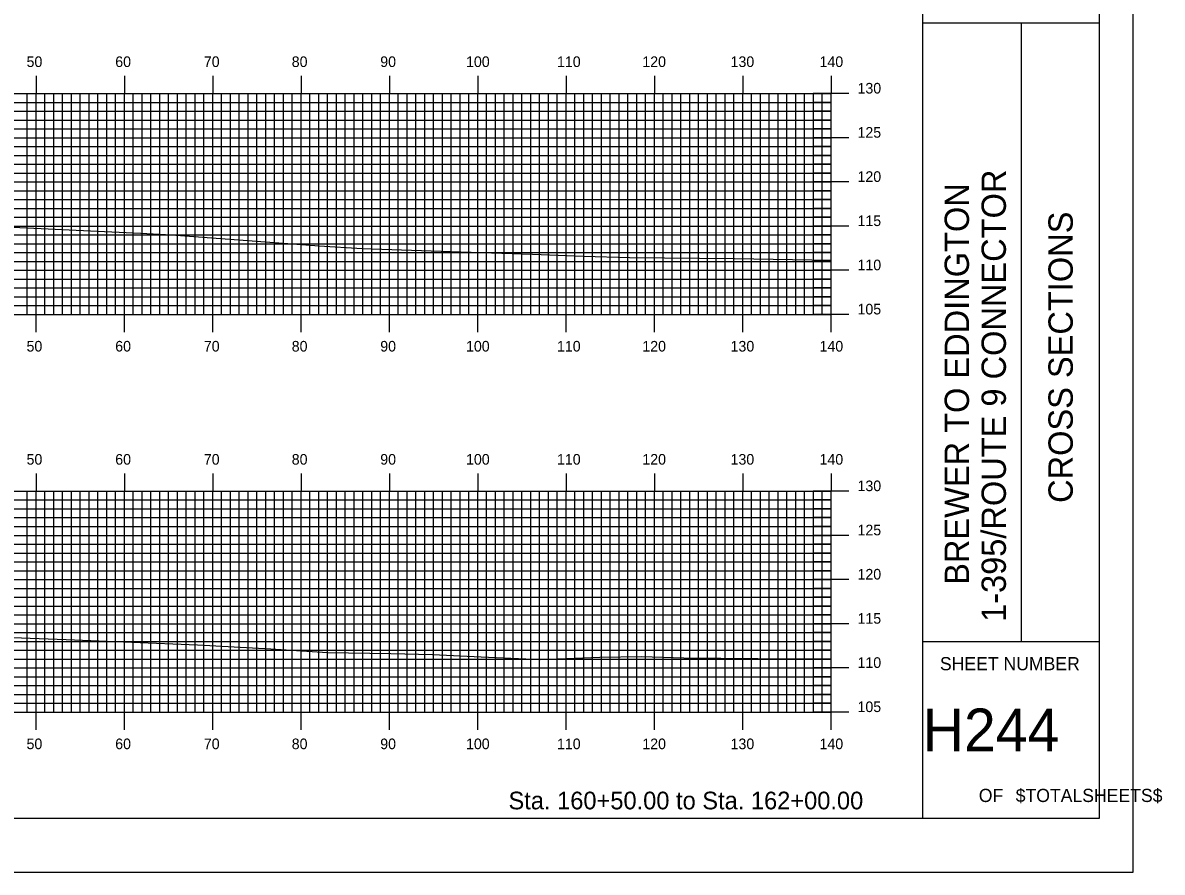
# Model space of a CAD drawing. Extents: x 1780286 to 1780629, y 442591 to 442811.
# Drawn here: x 1780500.4 to 1780629.4, y 442590.5 to 442686.7 of the extents above; entities that cross this region are included whole.
import ezdxf

# ---------------------------------------------------------------- set-up
doc = ezdxf.new("R2010")
doc.units = 0
for name, color, linetype in [('BORDER', 7, 'Continuous'), ('H_V ANNOTATION', 7, 'Continuous'), ('MAJOR', 7, 'Continuous'), ('MINOR', 7, 'Continuous'), ('PLOT BOUNDARY', 7, 'Continuous'), ('S_Roadway_Centerline', 7, 'Continuous')]:
    doc.layers.add(name, color=color, linetype=linetype)

msp = doc.modelspace()

# ---------------------------------------------------------------- linework, layer by layer
at = {"layer": 'BORDER'}
for p, q in [((1780602.27, 442596.67), (1780602.27, 442806.67)), ((1780602.27, 442686.67), (1780622.27, 442686.67)), ((1780613.45, 442616.67), (1780613.45, 442686.67)), ((1780602.27, 442616.67), (1780622.27, 442616.67))]:
    msp.add_line(p, q, dxfattribs=at)
msp.add_lwpolyline([(1780302.27, 442596.67), (1780622.27, 442596.67), (1780622.27, 442806.67), (1780302.27, 442806.67)], close=True, dxfattribs=at)
at = {"layer": 'MAJOR'}
for p, q in [((1780501.87, 442680.67), (1780501.87, 442678.67)), ((1780511.87, 442680.67), (1780511.87, 442678.67)), ((1780521.87, 442680.67), (1780521.87, 442678.67)), ((1780531.87, 442680.67), (1780531.87, 442678.67)), ((1780541.87, 442680.67), (1780541.87, 442678.67)), ((1780551.87, 442680.67), (1780551.87, 442678.67)), ((1780561.87, 442680.67), (1780561.87, 442678.67)), ((1780571.87, 442680.67), (1780571.87, 442678.67)), ((1780581.87, 442680.67), (1780581.87, 442678.67)), ((1780591.87, 442680.67), (1780591.87, 442678.67)), ((1780311.87, 442678.67), (1780591.87, 442678.67)), ((1780311.87, 442678.67), (1780591.87, 442678.67)), ((1780501.87, 442653.67), (1780501.87, 442678.67)), ((1780511.87, 442653.67), (1780511.87, 442678.67)), ((1780521.87, 442653.67), (1780521.87, 442678.67)), ((1780531.87, 442653.67), (1780531.87, 442678.67)), ((1780541.87, 442653.67), (1780541.87, 442678.67)), ((1780551.87, 442653.67), (1780551.87, 442678.67)), ((1780561.87, 442653.67), (1780561.87, 442678.67)), ((1780571.87, 442653.67), (1780571.87, 442678.67)), ((1780581.87, 442653.67), (1780581.87, 442678.67)), ((1780593.87, 442678.67), (1780589.86, 442678.67)), ((1780591.87, 442653.67), (1780591.87, 442678.67)), ((1780591.87, 442653.67), (1780591.87, 442678.67)), ((1780311.87, 442673.67), (1780591.87, 442673.67)), ((1780593.87, 442673.67), (1780589.86, 442673.67)), ((1780311.87, 442668.67), (1780591.87, 442668.67)), ((1780593.87, 442668.67), (1780589.86, 442668.67)), ((1780311.87, 442663.67), (1780591.87, 442663.67)), ((1780593.87, 442663.67), (1780589.86, 442663.67)), ((1780311.87, 442658.67), (1780591.87, 442658.67)), ((1780593.87, 442658.67), (1780589.86, 442658.67)), ((1780311.87, 442653.67), (1780591.87, 442653.67)), ((1780311.87, 442653.67), (1780591.87, 442653.67)), ((1780501.87, 442651.66), (1780501.87, 442653.67)), ((1780511.87, 442651.66), (1780511.87, 442653.67)), ((1780521.87, 442651.66), (1780521.87, 442653.67)), ((1780531.87, 442651.66), (1780531.87, 442653.67)), ((1780541.87, 442651.66), (1780541.87, 442653.67)), ((1780551.87, 442651.66), (1780551.87, 442653.67)), ((1780561.87, 442651.66), (1780561.87, 442653.67)), ((1780571.87, 442651.66), (1780571.87, 442653.67)), ((1780581.87, 442651.66), (1780581.87, 442653.67)), ((1780593.87, 442653.67), (1780589.86, 442653.67)), ((1780591.87, 442651.66), (1780591.87, 442653.67)), ((1780501.87, 442635.67), (1780501.87, 442633.67)), ((1780511.87, 442635.67), (1780511.87, 442633.67)), ((1780521.87, 442635.67), (1780521.87, 442633.67)), ((1780531.87, 442635.67), (1780531.87, 442633.67)), ((1780541.87, 442635.67), (1780541.87, 442633.67)), ((1780551.87, 442635.67), (1780551.87, 442633.67)), ((1780561.87, 442635.67), (1780561.87, 442633.67)), ((1780571.87, 442635.67), (1780571.87, 442633.67)), ((1780581.87, 442635.67), (1780581.87, 442633.67)), ((1780591.87, 442635.67), (1780591.87, 442633.67)), ((1780311.87, 442633.67), (1780591.87, 442633.67)), ((1780311.87, 442633.67), (1780591.87, 442633.67)), ((1780501.87, 442608.67), (1780501.87, 442633.67)), ((1780511.87, 442608.67), (1780511.87, 442633.67)), ((1780521.87, 442608.67), (1780521.87, 442633.67)), ((1780531.87, 442608.67), (1780531.87, 442633.67)), ((1780541.87, 442608.67), (1780541.87, 442633.67)), ((1780551.87, 442608.67), (1780551.87, 442633.67)), ((1780561.87, 442608.67), (1780561.87, 442633.67)), ((1780571.87, 442608.67), (1780571.87, 442633.67)), ((1780581.87, 442608.67), (1780581.87, 442633.67)), ((1780593.87, 442633.67), (1780589.86, 442633.67)), ((1780591.87, 442608.67), (1780591.87, 442633.67)), ((1780591.87, 442608.67), (1780591.87, 442633.67)), ((1780311.87, 442628.67), (1780591.87, 442628.67)), ((1780593.87, 442628.67), (1780589.86, 442628.67)), ((1780311.87, 442623.67), (1780591.87, 442623.67)), ((1780593.87, 442623.67), (1780589.86, 442623.67)), ((1780311.87, 442618.67), (1780591.87, 442618.67)), ((1780593.87, 442618.67), (1780589.86, 442618.67)), ((1780311.87, 442613.67), (1780591.87, 442613.67)), ((1780593.87, 442613.67), (1780589.86, 442613.67)), ((1780311.87, 442608.67), (1780591.87, 442608.67)), ((1780311.87, 442608.67), (1780591.87, 442608.67)), ((1780501.87, 442606.66), (1780501.87, 442608.67)), ((1780511.87, 442606.66), (1780511.87, 442608.67)), ((1780521.87, 442606.66), (1780521.87, 442608.67)), ((1780531.87, 442606.66), (1780531.87, 442608.67)), ((1780541.87, 442606.66), (1780541.87, 442608.67)), ((1780551.87, 442606.66), (1780551.87, 442608.67)), ((1780561.87, 442606.66), (1780561.87, 442608.67)), ((1780571.87, 442606.66), (1780571.87, 442608.67)), ((1780581.87, 442606.66), (1780581.87, 442608.67)), ((1780593.87, 442608.67), (1780589.86, 442608.67)), ((1780591.87, 442606.66), (1780591.87, 442608.67))]:
    msp.add_line(p, q, dxfattribs=at)
at = {"layer": 'MINOR'}
for p, q in [((1780500.87, 442653.67), (1780500.87, 442678.67)), ((1780502.87, 442653.67), (1780502.87, 442678.67)), ((1780503.87, 442653.67), (1780503.87, 442678.67)), ((1780504.87, 442653.67), (1780504.87, 442678.67)), ((1780505.87, 442653.67), (1780505.87, 442678.67)), ((1780506.87, 442653.67), (1780506.87, 442678.67)), ((1780507.87, 442653.67), (1780507.87, 442678.67)), ((1780508.87, 442653.67), (1780508.87, 442678.67)), ((1780509.87, 442653.67), (1780509.87, 442678.67)), ((1780510.87, 442653.67), (1780510.87, 442678.67)), ((1780512.87, 442653.67), (1780512.87, 442678.67)), ((1780513.87, 442653.67), (1780513.87, 442678.67)), ((1780514.87, 442653.67), (1780514.87, 442678.67)), ((1780515.87, 442653.67), (1780515.87, 442678.67)), ((1780516.87, 442653.67), (1780516.87, 442678.67)), ((1780517.87, 442653.67), (1780517.87, 442678.67)), ((1780518.87, 442653.67), (1780518.87, 442678.67)), ((1780519.87, 442653.67), (1780519.87, 442678.67)), ((1780520.87, 442653.67), (1780520.87, 442678.67)), ((1780522.87, 442653.67), (1780522.87, 442678.67)), ((1780523.87, 442653.67), (1780523.87, 442678.67)), ((1780524.87, 442653.67), (1780524.87, 442678.67)), ((1780525.87, 442653.67), (1780525.87, 442678.67)), ((1780526.87, 442653.67), (1780526.87, 442678.67)), ((1780527.87, 442653.67), (1780527.87, 442678.67)), ((1780528.87, 442653.67), (1780528.87, 442678.67)), ((1780529.87, 442653.67), (1780529.87, 442678.67)), ((1780530.87, 442653.67), (1780530.87, 442678.67)), ((1780532.87, 442653.67), (1780532.87, 442678.67)), ((1780533.87, 442653.67), (1780533.87, 442678.67)), ((1780534.87, 442653.67), (1780534.87, 442678.67)), ((1780535.87, 442653.67), (1780535.87, 442678.67)), ((1780536.87, 442653.67), (1780536.87, 442678.67)), ((1780537.87, 442653.67), (1780537.87, 442678.67)), ((1780538.87, 442653.67), (1780538.87, 442678.67)), ((1780539.87, 442653.67), (1780539.87, 442678.67)), ((1780540.87, 442653.67), (1780540.87, 442678.67)), ((1780542.87, 442653.67), (1780542.87, 442678.67)), ((1780543.87, 442653.67), (1780543.87, 442678.67)), ((1780544.87, 442653.67), (1780544.87, 442678.67)), ((1780545.87, 442653.67), (1780545.87, 442678.67)), ((1780546.87, 442653.67), (1780546.87, 442678.67)), ((1780547.87, 442653.67), (1780547.87, 442678.67)), ((1780548.87, 442653.67), (1780548.87, 442678.67)), ((1780549.87, 442653.67), (1780549.87, 442678.67)), ((1780550.87, 442653.67), (1780550.87, 442678.67)), ((1780552.87, 442653.67), (1780552.87, 442678.67)), ((1780553.87, 442653.67), (1780553.87, 442678.67)), ((1780554.87, 442653.67), (1780554.87, 442678.67)), ((1780555.87, 442653.67), (1780555.87, 442678.67)), ((1780556.87, 442653.67), (1780556.87, 442678.67)), ((1780557.87, 442653.67), (1780557.87, 442678.67)), ((1780558.87, 442653.67), (1780558.87, 442678.67)), ((1780559.87, 442653.67), (1780559.87, 442678.67)), ((1780560.87, 442653.67), (1780560.87, 442678.67)), ((1780562.87, 442653.67), (1780562.87, 442678.67)), ((1780563.87, 442653.67), (1780563.87, 442678.67)), ((1780564.87, 442653.67), (1780564.87, 442678.67)), ((1780565.87, 442653.67), (1780565.87, 442678.67)), ((1780566.87, 442653.67), (1780566.87, 442678.67)), ((1780567.87, 442653.67), (1780567.87, 442678.67)), ((1780568.87, 442653.67), (1780568.87, 442678.67)), ((1780569.87, 442653.67), (1780569.87, 442678.67)), ((1780570.87, 442653.67), (1780570.87, 442678.67)), ((1780572.87, 442653.67), (1780572.87, 442678.67)), ((1780573.87, 442653.67), (1780573.87, 442678.67)), ((1780574.87, 442653.67), (1780574.87, 442678.67)), ((1780575.87, 442653.67), (1780575.87, 442678.67)), ((1780576.87, 442653.67), (1780576.87, 442678.67)), ((1780577.87, 442653.67), (1780577.87, 442678.67)), ((1780578.87, 442653.67), (1780578.87, 442678.67)), ((1780579.87, 442653.67), (1780579.87, 442678.67)), ((1780580.87, 442653.67), (1780580.87, 442678.67)), ((1780582.87, 442653.67), (1780582.87, 442678.67)), ((1780583.87, 442653.67), (1780583.87, 442678.67)), ((1780584.87, 442653.67), (1780584.87, 442678.67)), ((1780585.87, 442653.67), (1780585.87, 442678.67)), ((1780586.87, 442653.67), (1780586.87, 442678.67)), ((1780587.87, 442653.67), (1780587.87, 442678.67)), ((1780588.87, 442653.67), (1780588.87, 442678.67)), ((1780589.87, 442653.67), (1780589.87, 442678.67)), ((1780590.87, 442653.67), (1780590.87, 442678.67)), ((1780311.87, 442677.67), (1780591.87, 442677.67)), ((1780591.87, 442677.67), (1780589.86, 442677.67)), ((1780311.87, 442676.67), (1780591.87, 442676.67)), ((1780591.87, 442676.67), (1780589.86, 442676.67)), ((1780311.87, 442675.67), (1780591.87, 442675.67)), ((1780311.87, 442674.67), (1780591.87, 442674.67)), ((1780591.87, 442675.67), (1780589.86, 442675.67)), ((1780591.87, 442674.67), (1780589.86, 442674.67)), ((1780311.87, 442672.67), (1780591.87, 442672.67)), ((1780591.87, 442672.67), (1780589.86, 442672.67)), ((1780311.87, 442671.67), (1780591.87, 442671.67)), ((1780311.87, 442670.67), (1780591.87, 442670.67)), ((1780591.87, 442671.67), (1780589.86, 442671.67)), ((1780591.87, 442670.67), (1780589.86, 442670.67)), ((1780311.87, 442669.67), (1780591.87, 442669.67)), ((1780591.87, 442669.67), (1780589.86, 442669.67)), ((1780311.87, 442667.67), (1780591.87, 442667.67)), ((1780591.87, 442667.67), (1780589.86, 442667.67)), ((1780311.87, 442666.67), (1780591.87, 442666.67)), ((1780311.87, 442665.67), (1780591.87, 442665.67)), ((1780591.87, 442666.67), (1780589.86, 442666.67)), ((1780591.87, 442665.67), (1780589.86, 442665.67)), ((1780311.87, 442664.67), (1780591.87, 442664.67)), ((1780591.87, 442664.67), (1780589.86, 442664.67)), ((1780311.87, 442662.67), (1780591.87, 442662.67)), ((1780311.87, 442661.67), (1780591.87, 442661.67)), ((1780591.87, 442662.67), (1780589.86, 442662.67)), ((1780591.87, 442661.67), (1780589.86, 442661.67)), ((1780311.87, 442660.67), (1780591.87, 442660.67)), ((1780591.87, 442660.67), (1780589.86, 442660.67)), ((1780311.87, 442659.67), (1780591.87, 442659.67)), ((1780591.87, 442659.67), (1780589.86, 442659.67)), ((1780311.87, 442657.67), (1780591.87, 442657.67)), ((1780311.87, 442656.67), (1780591.87, 442656.67)), ((1780591.87, 442657.67), (1780589.86, 442657.67)), ((1780591.87, 442656.67), (1780589.86, 442656.67)), ((1780311.87, 442655.67), (1780591.87, 442655.67)), ((1780591.87, 442655.67), (1780589.86, 442655.67)), ((1780311.87, 442654.67), (1780591.87, 442654.67)), ((1780591.87, 442654.67), (1780589.86, 442654.67)), ((1780500.87, 442608.67), (1780500.87, 442633.67)), ((1780502.87, 442608.67), (1780502.87, 442633.67)), ((1780503.87, 442608.67), (1780503.87, 442633.67)), ((1780504.87, 442608.67), (1780504.87, 442633.67)), ((1780505.87, 442608.67), (1780505.87, 442633.67)), ((1780506.87, 442608.67), (1780506.87, 442633.67)), ((1780507.87, 442608.67), (1780507.87, 442633.67)), ((1780508.87, 442608.67), (1780508.87, 442633.67)), ((1780509.87, 442608.67), (1780509.87, 442633.67)), ((1780510.87, 442608.67), (1780510.87, 442633.67)), ((1780512.87, 442608.67), (1780512.87, 442633.67)), ((1780513.87, 442608.67), (1780513.87, 442633.67)), ((1780514.87, 442608.67), (1780514.87, 442633.67)), ((1780515.87, 442608.67), (1780515.87, 442633.67)), ((1780516.87, 442608.67), (1780516.87, 442633.67)), ((1780517.87, 442608.67), (1780517.87, 442633.67)), ((1780518.87, 442608.67), (1780518.87, 442633.67)), ((1780519.87, 442608.67), (1780519.87, 442633.67)), ((1780520.87, 442608.67), (1780520.87, 442633.67)), ((1780522.87, 442608.67), (1780522.87, 442633.67)), ((1780523.87, 442608.67), (1780523.87, 442633.67)), ((1780524.87, 442608.67), (1780524.87, 442633.67)), ((1780525.87, 442608.67), (1780525.87, 442633.67)), ((1780526.87, 442608.67), (1780526.87, 442633.67)), ((1780527.87, 442608.67), (1780527.87, 442633.67)), ((1780528.87, 442608.67), (1780528.87, 442633.67)), ((1780529.87, 442608.67), (1780529.87, 442633.67)), ((1780530.87, 442608.67), (1780530.87, 442633.67)), ((1780532.87, 442608.67), (1780532.87, 442633.67)), ((1780533.87, 442608.67), (1780533.87, 442633.67)), ((1780534.87, 442608.67), (1780534.87, 442633.67)), ((1780535.87, 442608.67), (1780535.87, 442633.67)), ((1780536.87, 442608.67), (1780536.87, 442633.67)), ((1780537.87, 442608.67), (1780537.87, 442633.67)), ((1780538.87, 442608.67), (1780538.87, 442633.67)), ((1780539.87, 442608.67), (1780539.87, 442633.67)), ((1780540.87, 442608.67), (1780540.87, 442633.67)), ((1780542.87, 442608.67), (1780542.87, 442633.67)), ((1780543.87, 442608.67), (1780543.87, 442633.67)), ((1780544.87, 442608.67), (1780544.87, 442633.67)), ((1780545.87, 442608.67), (1780545.87, 442633.67)), ((1780546.87, 442608.67), (1780546.87, 442633.67)), ((1780547.87, 442608.67), (1780547.87, 442633.67)), ((1780548.87, 442608.67), (1780548.87, 442633.67)), ((1780549.87, 442608.67), (1780549.87, 442633.67)), ((1780550.87, 442608.67), (1780550.87, 442633.67)), ((1780552.87, 442608.67), (1780552.87, 442633.67)), ((1780553.87, 442608.67), (1780553.87, 442633.67)), ((1780554.87, 442608.67), (1780554.87, 442633.67)), ((1780555.87, 442608.67), (1780555.87, 442633.67)), ((1780556.87, 442608.67), (1780556.87, 442633.67)), ((1780557.87, 442608.67), (1780557.87, 442633.67)), ((1780558.87, 442608.67), (1780558.87, 442633.67)), ((1780559.87, 442608.67), (1780559.87, 442633.67)), ((1780560.87, 442608.67), (1780560.87, 442633.67)), ((1780562.87, 442608.67), (1780562.87, 442633.67)), ((1780563.87, 442608.67), (1780563.87, 442633.67)), ((1780564.87, 442608.67), (1780564.87, 442633.67)), ((1780565.87, 442608.67), (1780565.87, 442633.67)), ((1780566.87, 442608.67), (1780566.87, 442633.67)), ((1780567.87, 442608.67), (1780567.87, 442633.67)), ((1780568.87, 442608.67), (1780568.87, 442633.67)), ((1780569.87, 442608.67), (1780569.87, 442633.67)), ((1780570.87, 442608.67), (1780570.87, 442633.67)), ((1780572.87, 442608.67), (1780572.87, 442633.67)), ((1780573.87, 442608.67), (1780573.87, 442633.67)), ((1780574.87, 442608.67), (1780574.87, 442633.67)), ((1780575.87, 442608.67), (1780575.87, 442633.67)), ((1780576.87, 442608.67), (1780576.87, 442633.67)), ((1780577.87, 442608.67), (1780577.87, 442633.67)), ((1780578.87, 442608.67), (1780578.87, 442633.67)), ((1780579.87, 442608.67), (1780579.87, 442633.67)), ((1780580.87, 442608.67), (1780580.87, 442633.67)), ((1780582.87, 442608.67), (1780582.87, 442633.67)), ((1780583.87, 442608.67), (1780583.87, 442633.67)), ((1780584.87, 442608.67), (1780584.87, 442633.67)), ((1780585.87, 442608.67), (1780585.87, 442633.67)), ((1780586.87, 442608.67), (1780586.87, 442633.67)), ((1780587.87, 442608.67), (1780587.87, 442633.67)), ((1780588.87, 442608.67), (1780588.87, 442633.67)), ((1780589.87, 442608.67), (1780589.87, 442633.67)), ((1780590.87, 442608.67), (1780590.87, 442633.67)), ((1780311.87, 442632.67), (1780591.87, 442632.67)), ((1780591.87, 442632.67), (1780589.86, 442632.67)), ((1780311.87, 442631.67), (1780591.87, 442631.67)), ((1780311.87, 442630.67), (1780591.87, 442630.67)), ((1780591.87, 442631.67), (1780589.86, 442631.67)), ((1780591.87, 442630.67), (1780589.86, 442630.67)), ((1780311.87, 442629.67), (1780591.87, 442629.67)), ((1780591.87, 442629.67), (1780589.86, 442629.67)), ((1780311.87, 442627.67), (1780591.87, 442627.67)), ((1780591.87, 442627.67), (1780589.86, 442627.67)), ((1780311.87, 442626.67), (1780591.87, 442626.67)), ((1780311.87, 442625.67), (1780591.87, 442625.67)), ((1780591.87, 442626.67), (1780589.86, 442626.67)), ((1780591.87, 442625.67), (1780589.86, 442625.67)), ((1780311.87, 442624.67), (1780591.87, 442624.67)), ((1780591.87, 442624.67), (1780589.86, 442624.67)), ((1780311.87, 442622.67), (1780591.87, 442622.67)), ((1780311.87, 442621.67), (1780591.87, 442621.67)), ((1780591.87, 442622.67), (1780589.86, 442622.67)), ((1780591.87, 442621.67), (1780589.86, 442621.67)), ((1780311.87, 442620.67), (1780591.87, 442620.67)), ((1780591.87, 442620.67), (1780589.86, 442620.67)), ((1780311.87, 442619.67), (1780591.87, 442619.67)), ((1780591.87, 442619.67), (1780589.86, 442619.67)), ((1780311.87, 442617.67), (1780591.87, 442617.67)), ((1780311.87, 442616.67), (1780591.87, 442616.67)), ((1780591.87, 442617.67), (1780589.86, 442617.67)), ((1780591.87, 442616.67), (1780589.86, 442616.67)), ((1780311.87, 442615.67), (1780591.87, 442615.67)), ((1780591.87, 442615.67), (1780589.86, 442615.67)), ((1780311.87, 442614.67), (1780591.87, 442614.67)), ((1780591.87, 442614.67), (1780589.86, 442614.67)), ((1780311.87, 442612.67), (1780591.87, 442612.67)), ((1780591.87, 442612.67), (1780589.86, 442612.67)), ((1780311.87, 442611.67), (1780591.87, 442611.67)), ((1780591.87, 442611.67), (1780589.86, 442611.67)), ((1780311.87, 442610.67), (1780591.87, 442610.67)), ((1780591.87, 442610.67), (1780589.86, 442610.67)), ((1780311.87, 442609.67), (1780591.87, 442609.67)), ((1780591.87, 442609.67), (1780589.86, 442609.67))]:
    msp.add_line(p, q, dxfattribs=at)
at = {"layer": 'PLOT BOUNDARY'}
msp.add_lwpolyline([(1780286.08, 442590.55), (1780626.08, 442590.55), (1780626.08, 442810.55), (1780286.08, 442810.55)], close=True, dxfattribs=at)
at = {"layer": 'S_Roadway_Centerline'}
for points in [[(1780489.63, 442663.98), (1780509.62, 442663.05), (1780513.74, 442662.86), (1780517.22, 442662.69), (1780533.92, 442661.45), (1780538.81, 442661.13), (1780549.95, 442660.75), (1780558.06, 442660.49), (1780563.89, 442660.25), (1780569.05, 442660.13), (1780580.95, 442660), (1780591.87, 442659.82)], [(1780496.12, 442617.22), (1780505.3, 442616.88), (1780520.17, 442616.28), (1780528.47, 442615.83), (1780534.88, 442615.4), (1780542.04, 442615.29), (1780546.76, 442615.17), (1780552.26, 442614.93), (1780559.01, 442614.6), (1780565.68, 442614.87), (1780570.4, 442614.96), (1780575.22, 442614.82), (1780587.78, 442614.71), (1780591.87, 442614.7)]]:
    msp.add_lwpolyline(points, dxfattribs=at)

# ---------------------------------------------------------------- texts
at = {"layer": 'BORDER'}
for s, p in [('1-395/ROUTE 9 CONNECTOR', (1780611.67, 442618.87)), ('BREWER TO EDDINGTON', (1780607.49, 442623.07)), ('CROSS SECTIONS', (1780619.24, 442632.34))]:
    msp.add_text(s, height=2.7557, rotation=90, dxfattribs=at).set_placement(p)
for s, height, p in [('SHEET NUMBER', 1.4905, (1780604.2, 442613.4)), ('H244', 4.839, (1780602.25, 442604.23)), ('OF', 1.491, (1780608.6, 442598.49)), ('$TOTALSHEETS$', 1.4905, (1780612.78, 442598.49))]:
    msp.add_text(s, height=height, dxfattribs=at).set_placement(p)
at = {"layer": 'H_V ANNOTATION'}
for s, height, p in [('50', 1.2, (1780500.8, 442681.67)), ('60', 1.2, (1780510.84, 442681.67)), ('70', 1.2, (1780520.87, 442681.67)), ('80', 1.2, (1780530.82, 442681.67)), ('90', 1.2, (1780540.84, 442681.67)), ('100', 1.2, (1780550.55, 442681.67)), ('110', 1.2, (1780560.85, 442681.67)), ('120', 1.2, (1780570.51, 442681.67)), ('130', 1.2, (1780580.5, 442681.67)), ('140', 1.2, (1780590.57, 442681.67)), ('130', 1.2, (1780594.87, 442678.67)), ('125', 1.2, (1780594.87, 442673.67)), ('120', 1.2, (1780594.87, 442668.67)), ('115', 1.2, (1780594.87, 442663.67)), ('110', 1.2, (1780594.87, 442658.67)), ('105', 1.2, (1780594.87, 442653.67)), ('50', 1.2, (1780500.8, 442649.47)), ('60', 1.2, (1780510.84, 442649.47)), ('70', 1.2, (1780520.87, 442649.47)), ('80', 1.2, (1780530.82, 442649.47)), ('90', 1.2, (1780540.84, 442649.47)), ('100', 1.2, (1780550.55, 442649.47)), ('110', 1.2, (1780560.85, 442649.47)), ('120', 1.2, (1780570.51, 442649.47)), ('130', 1.2, (1780580.5, 442649.47)), ('140', 1.2, (1780590.57, 442649.47)), ('50', 1.2, (1780500.8, 442636.67)), ('60', 1.2, (1780510.84, 442636.67)), ('70', 1.2, (1780520.87, 442636.67)), ('80', 1.2, (1780530.82, 442636.67)), ('90', 1.2, (1780540.84, 442636.67)), ('100', 1.2, (1780550.55, 442636.67)), ('110', 1.2, (1780560.85, 442636.67)), ('120', 1.2, (1780570.51, 442636.67)), ('130', 1.2, (1780580.5, 442636.67)), ('140', 1.2, (1780590.57, 442636.67)), ('130', 1.2, (1780594.87, 442633.67)), ('125', 1.2, (1780594.87, 442628.67)), ('120', 1.2, (1780594.87, 442623.67)), ('115', 1.2, (1780594.87, 442618.67)), ('110', 1.2, (1780594.87, 442613.67)), ('105', 1.2, (1780594.87, 442608.67)), ('50', 1.2, (1780500.8, 442604.47)), ('60', 1.2, (1780510.84, 442604.47)), ('70', 1.2, (1780520.87, 442604.47)), ('80', 1.2, (1780530.82, 442604.47)), ('90', 1.2, (1780540.84, 442604.47)), ('100', 1.2, (1780550.55, 442604.47)), ('110', 1.2, (1780560.85, 442604.47)), ('120', 1.2, (1780570.51, 442604.47)), ('130', 1.2, (1780580.5, 442604.47)), ('140', 1.2, (1780590.57, 442604.47)), ('Sta. 160+50.00 to Sta. 162+00.00', 2.0004, (1780555.36, 442597.66))]:
    msp.add_text(s, height=height, dxfattribs=at).set_placement(p)

doc.saveas('drawing.dxf')
